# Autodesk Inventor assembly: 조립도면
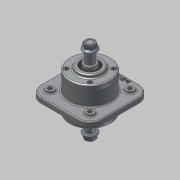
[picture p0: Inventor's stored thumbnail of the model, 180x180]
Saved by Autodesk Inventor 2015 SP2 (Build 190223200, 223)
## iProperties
Created: 2015-07
Part Number: 조립도면
Document SubType Name: Assembly
Designer: AMC
Author: AMC
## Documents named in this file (12)
- C:\Users\AMC\Desktop\450735V1001\조립도면.iam
- C:\Users\AMC\Desktop\450735V1001\2-커버.ipt
- C:\Users\AMC\Desktop\450735V1001\3-축.ipt
- C:\Users\AMC\Desktop\450735V1001\4-V벨트풀리.ipt
- C:\Users\AMC\Desktop\450735V1001\5-체인 스프로킷.ipt
- C:\Users\AMC\Desktop\450735V1001\6-베어링 6206.ipt
- C:\Users\AMC\Desktop\450735V1001\7-부시.ipt
- C:\Users\AMC\Desktop\450735V1001\8-오일실 30x42.ipt
- C:\Users\AMC\Desktop\450735V1001\9-M16-너트.ipt
- C:\Users\AMC\Desktop\450735V1001\10-M6.ipt
- C:\Users\AMC\Desktop\450735V1001\11-키 6x6.ipt
- C:\Users\AMC\Desktop\450735V1001\본체.ipt
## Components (22 placed, 10 different names)
1. 2-커버:1
2. 3-축:1
3. 4-V벨트풀리:1
4. 5-체인 스프로킷:1
5. 6-베어링 6206:1
6. 7-부시:1 — 플러쉬:4
7. 8-8-오일실 30x42:1
8. 9-M16 너트:1
9. 10-M6:1
10. 11-키 6x6:1
11. 2-커버:2
12. 6-베어링 6206:2
13. 8-8-오일실 30x42:2
14. 9-M16 너트:2
15. 10-M6:2
16. 10-M6:3
17. 10-M6:4
18. 10-M6:5
19. 10-M6:6
20. 10-M6:7
21. 10-M6:8
22. 11-키 6x6:2
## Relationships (1: Flush 1)
- 플러쉬:4 [Flush]: 7-부시:1
